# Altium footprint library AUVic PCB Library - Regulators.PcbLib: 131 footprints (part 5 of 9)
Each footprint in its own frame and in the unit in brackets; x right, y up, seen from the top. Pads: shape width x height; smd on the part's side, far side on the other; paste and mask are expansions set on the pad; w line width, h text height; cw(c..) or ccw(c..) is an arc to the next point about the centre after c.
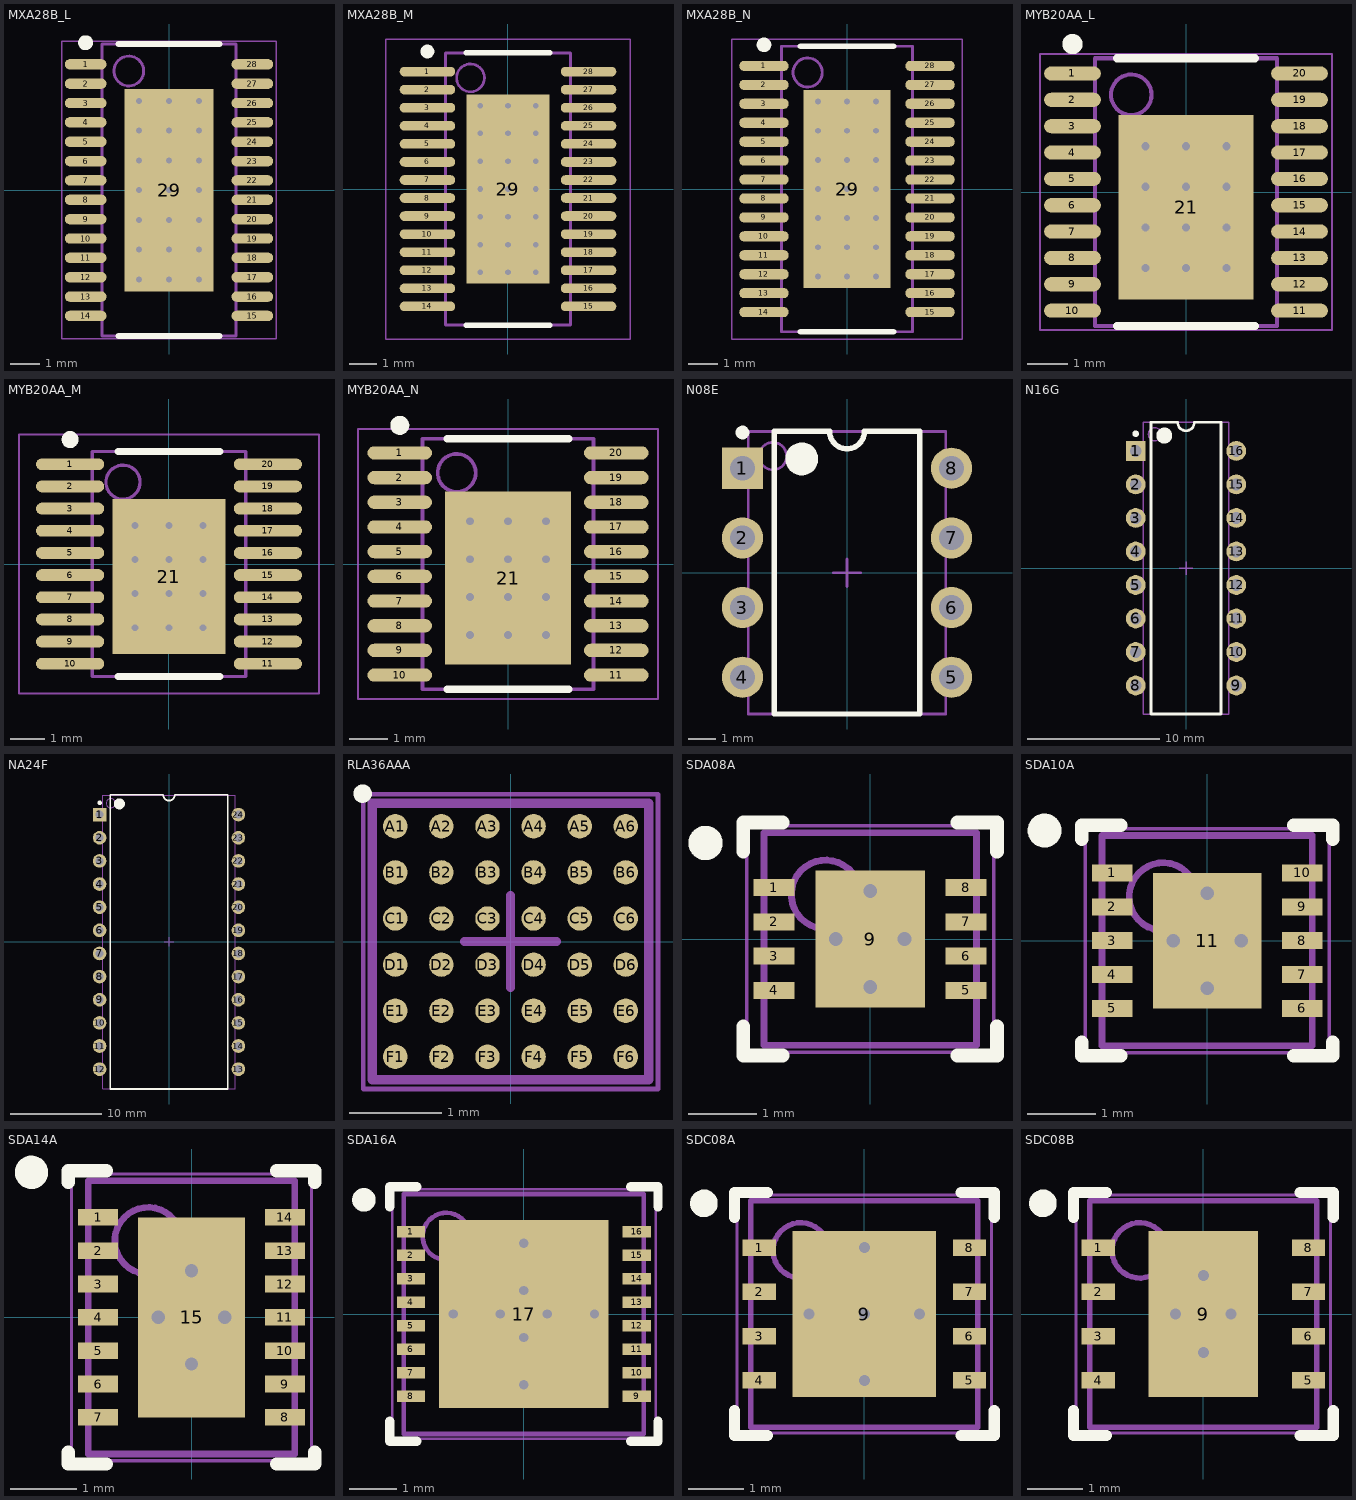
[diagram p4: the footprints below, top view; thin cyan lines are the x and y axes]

## MXA28B_L [mm] "TSOP, 28-Leads, Body 9.7x4.4mm, Pitch 0.65mm, Thermal Pad, IPC High Density"
height 1.1
pads (29):
  oval 1.4x0.35 smd: 1(-2.8,4.225) 2(-2.8,3.575) 3(-2.8,2.925) 4(-2.8,2.275) 5(-2.8,1.625) 6(-2.8,0.975) 7(-2.8,0.325) 8(-2.8,-0.325) 9(-2.8,-0.975) 10(-2.8,-1.625) 11(-2.8,-2.275) 12(-2.8,-2.925) 13(-2.8,-3.575) 14(-2.8,-4.225) 15(2.8,-4.225) 16(2.8,-3.575) 17(2.8,-2.925) 18(2.8,-2.275) 19(2.8,-1.625) 20(2.8,-0.975) 21(2.8,-0.325) 22(2.8,0.325) 23(2.8,0.975) 24(2.8,1.625) 25(2.8,2.275) 26(2.8,2.925) 27(2.8,3.575) 28(2.8,4.225)
  rect 3x6.8 smd: 29(0,0)
via 1,3 diameter 0.4 hole 0.2
via 0,3 diameter 0.4 hole 0.2
via -1,3 diameter 0.4 hole 0.2
via 0,0 diameter 0.4 hole 0.2
via 1,0 diameter 0.4 hole 0.2
via 0,-1 diameter 0.4 hole 0.2
via 1,-1 diameter 0.4 hole 0.2
via 0,-2 diameter 0.4 hole 0.2
via 1,-2 diameter 0.4 hole 0.2
via 1,1 diameter 0.4 hole 0.2
via 0,1 diameter 0.4 hole 0.2
via 1,-3 diameter 0.4 hole 0.2
via 0,-3 diameter 0.4 hole 0.2
via -1,-3 diameter 0.4 hole 0.2
via -1,1 diameter 0.4 hole 0.2
via -1,-2 diameter 0.4 hole 0.2
via -1,-1 diameter 0.4 hole 0.2
via -1,0 diameter 0.4 hole 0.2
via -1,2 diameter 0.4 hole 0.2
via 0,2 diameter 0.4 hole 0.2
via 1,2 diameter 0.4 hole 0.2
Top Overlay:
  circle w0.25: c-2.8,4.95 r0.125
  lines w0.2: -1.7,-4.9 1.7,-4.9 ; -1.7,4.9 1.7,4.9
Mechanical 13:
  circle w0.1: c-1.35,4 r0.5
  lines w0.1: -2.25,-4.9 -2.25,4.9 2.25,4.9 2.25,-4.9 -2.25,-4.9
Mechanical 15:
  lines w0.05: -3.6,-5 -3.6,5 3.6,5 3.6,-5 -3.6,-5
  lines w0.1: -0.5,0 0.5,0 ; 0,-0.5 0,0.5
3D body: height 1.1, standoff 0.05, extent -2.25,-4.9 2.25,4.9

## MXA28B_M [mm] "TSOP, 28-Leads, Body 9.7x4.4mm, Pitch 0.65mm, Thermal Pad, IPC Low Density"
height 1.1
pads (29):
  oval 2x0.35 smd: 1(-2.9,4.225) 2(-2.9,3.575) 3(-2.9,2.925) 4(-2.9,2.275) 5(-2.9,1.625) 6(-2.9,0.975) 7(-2.9,0.325) 8(-2.9,-0.325) 9(-2.9,-0.975) 10(-2.9,-1.625) 11(-2.9,-2.275) 12(-2.9,-2.925) 13(-2.9,-3.575) 14(-2.9,-4.225) 15(2.9,-4.225) 16(2.9,-3.575) 17(2.9,-2.925) 18(2.9,-2.275) 19(2.9,-1.625) 20(2.9,-0.975) 21(2.9,-0.325) 22(2.9,0.325) 23(2.9,0.975) 24(2.9,1.625) 25(2.9,2.275) 26(2.9,2.925) 27(2.9,3.575) 28(2.9,4.225)
  rect 3x6.8 smd: 29(0,0)
via 1,3 diameter 0.4 hole 0.2
via 0,3 diameter 0.4 hole 0.2
via -1,3 diameter 0.4 hole 0.2
via 0,0 diameter 0.4 hole 0.2
via 1,0 diameter 0.4 hole 0.2
via 0,-1 diameter 0.4 hole 0.2
via 1,-1 diameter 0.4 hole 0.2
via 0,-2 diameter 0.4 hole 0.2
via 1,-2 diameter 0.4 hole 0.2
via 1,1 diameter 0.4 hole 0.2
via 0,1 diameter 0.4 hole 0.2
via 1,-3 diameter 0.4 hole 0.2
via 0,-3 diameter 0.4 hole 0.2
via -1,-3 diameter 0.4 hole 0.2
via -1,1 diameter 0.4 hole 0.2
via -1,-2 diameter 0.4 hole 0.2
via -1,-1 diameter 0.4 hole 0.2
via -1,0 diameter 0.4 hole 0.2
via -1,2 diameter 0.4 hole 0.2
via 0,2 diameter 0.4 hole 0.2
via 1,2 diameter 0.4 hole 0.2
Top Overlay:
  circle w0.25: c-2.9,4.95 r0.125
  lines w0.2: -1.5,-4.9 1.5,-4.9 ; -1.5,4.9 1.5,4.9
Mechanical 13:
  circle w0.1: c-1.35,4 r0.5
  lines w0.1: -2.25,-4.9 -2.25,4.9 2.25,4.9 2.25,-4.9 -2.25,-4.9
Mechanical 15:
  lines w0.05: -4.4,-5.4 -4.4,5.4 4.4,5.4 4.4,-5.4 -4.4,-5.4
  lines w0.1: -0.5,0 0.5,0 ; 0,-0.5 0,0.5
3D body: height 1.1, standoff 0.05, extent -2.25,-4.9 2.25,4.9

## MXA28B_N [mm] "TSOP, 28-Leads, Body 9.7x4.4mm, Pitch 0.65mm, Thermal Pad, IPC Medium Density"
height 1.1
pads (29):
  oval 1.7x0.35 smd: 1(-2.85,4.225) 2(-2.85,3.575) 3(-2.85,2.925) 4(-2.85,2.275) 5(-2.85,1.625) 6(-2.85,0.975) 7(-2.85,0.325) 8(-2.85,-0.325) 9(-2.85,-0.975) 10(-2.85,-1.625) 11(-2.85,-2.275) 12(-2.85,-2.925) 13(-2.85,-3.575) 14(-2.85,-4.225) 15(2.85,-4.225) 16(2.85,-3.575) 17(2.85,-2.925) 18(2.85,-2.275) 19(2.85,-1.625) 20(2.85,-0.975) 21(2.85,-0.325) 22(2.85,0.325) 23(2.85,0.975) 24(2.85,1.625) 25(2.85,2.275) 26(2.85,2.925) 27(2.85,3.575) 28(2.85,4.225)
  rect 3x6.8 smd: 29(0,0)
via 1,2 diameter 0.4 hole 0.2
via 0,2 diameter 0.4 hole 0.2
via -1,2 diameter 0.4 hole 0.2
via -1,0 diameter 0.4 hole 0.2
via -1,-1 diameter 0.4 hole 0.2
via -1,-2 diameter 0.4 hole 0.2
via -1,1 diameter 0.4 hole 0.2
via -1,-3 diameter 0.4 hole 0.2
via 0,-3 diameter 0.4 hole 0.2
via 1,-3 diameter 0.4 hole 0.2
via 0,1 diameter 0.4 hole 0.2
via 1,1 diameter 0.4 hole 0.2
via 1,-2 diameter 0.4 hole 0.2
via 0,-2 diameter 0.4 hole 0.2
via 1,-1 diameter 0.4 hole 0.2
via 0,-1 diameter 0.4 hole 0.2
via 1,0 diameter 0.4 hole 0.2
via 0,0 diameter 0.4 hole 0.2
via -1,3 diameter 0.4 hole 0.2
via 0,3 diameter 0.4 hole 0.2
via 1,3 diameter 0.4 hole 0.2
Top Overlay:
  circle w0.25: c-2.85,4.95 r0.125
  lines w0.2: -1.6,-4.9 1.6,-4.9 ; -1.6,4.9 1.6,4.9
Mechanical 13:
  circle w0.1: c-1.35,4 r0.5
  lines w0.1: -2.25,-4.9 2.25,-4.9 2.25,4.9 -2.25,4.9 -2.25,-4.9
Mechanical 15:
  lines w0.05: -3.95,-5.15 3.95,-5.15 3.95,5.15 -3.95,5.15 -3.95,-5.15
  lines w0.1: -0.5,0 0.5,0 ; 0,-0.5 0,0.5
3D body: height 1.1, standoff 0.05, extent -2.25,-4.9 2.25,4.9

## MYB20AA_L [mm] "TSOP, 20-Leads, Body 6.5x4.4mm, Pitch 0.65mm, Thermal Pad, IPC High Density"
height 1.1
pads (21):
  oval 1.4x0.35 smd: 1(-2.8,2.925) 2(-2.8,2.275) 3(-2.8,1.625) 4(-2.8,0.975) 5(-2.8,0.325) 6(-2.8,-0.325) 7(-2.8,-0.975) 8(-2.8,-1.625) 9(-2.8,-2.275) 10(-2.8,-2.925) 11(2.8,-2.925) 12(2.8,-2.275) 13(2.8,-1.625) 14(2.8,-0.975) 15(2.8,-0.325) 16(2.8,0.325) 17(2.8,0.975) 18(2.8,1.625) 19(2.8,2.275) 20(2.8,2.925)
  rect 3.32x4.55 smd: 21(0,-0.37)
via 0,0.13 diameter 0.5 hole 0.2
via 1,0.13 diameter 0.5 hole 0.2
via 0,-0.87 diameter 0.5 hole 0.2
via 1,-0.87 diameter 0.5 hole 0.2
via 0,-1.87 diameter 0.5 hole 0.2
via 1,-1.87 diameter 0.5 hole 0.2
via -1,-1.87 diameter 0.5 hole 0.2
via -1,-0.87 diameter 0.5 hole 0.2
via -1,0.13 diameter 0.5 hole 0.2
via -1,1.13 diameter 0.5 hole 0.2
via 1,1.13 diameter 0.5 hole 0.2
via 0,1.13 diameter 0.5 hole 0.2
Top Overlay:
  circle w0.25: c-2.8,3.65 r0.125
  lines w0.2: -1.7,-3.3 1.7,-3.3 ; -1.7,3.3 1.7,3.3
Mechanical 13:
  circle w0.1: c-1.35,2.4 r0.5
  lines w0.1: -2.25,-3.3 2.25,-3.3 2.25,3.3 -2.25,3.3 -2.25,-3.3
Mechanical 15:
  lines w0.05: -3.6,-3.4 3.6,-3.4 3.6,3.4 -3.6,3.4 -3.6,-3.4
  lines w0.1: -0.5,0 0.5,0 ; 0,-0.5 0,0.5
3D body: height 1.1, standoff 0.05, extent -2.25,-3.3 2.25,3.3

## MYB20AA_M [mm] "TSOP, 20-Leads, Body 6.5x4.4mm, Pitch 0.65mm, Thermal Pad, IPC Low Density"
height 1.1
pads (21):
  oval 2x0.35 smd: 1(-2.9,2.925) 2(-2.9,2.275) 3(-2.9,1.625) 4(-2.9,0.975) 5(-2.9,0.325) 6(-2.9,-0.325) 7(-2.9,-0.975) 8(-2.9,-1.625) 9(-2.9,-2.275) 10(-2.9,-2.925) 11(2.9,-2.925) 12(2.9,-2.275) 13(2.9,-1.625) 14(2.9,-0.975) 15(2.9,-0.325) 16(2.9,0.325) 17(2.9,0.975) 18(2.9,1.625) 19(2.9,2.275) 20(2.9,2.925)
  rect 3.32x4.55 smd: 21(0,-0.37)
via 0,1.13 diameter 0.5 hole 0.2
via 1,1.13 diameter 0.5 hole 0.2
via -1,1.13 diameter 0.5 hole 0.2
via -1,0.13 diameter 0.5 hole 0.2
via -1,-0.87 diameter 0.5 hole 0.2
via -1,-1.87 diameter 0.5 hole 0.2
via 1,-1.87 diameter 0.5 hole 0.2
via 0,-1.87 diameter 0.5 hole 0.2
via 1,-0.87 diameter 0.5 hole 0.2
via 0,-0.87 diameter 0.5 hole 0.2
via 1,0.13 diameter 0.5 hole 0.2
via 0,0.13 diameter 0.5 hole 0.2
Top Overlay:
  circle w0.25: c-2.9,3.65 r0.125
  lines w0.2: -1.5,-3.3 1.5,-3.3 ; -1.5,3.3 1.5,3.3
Mechanical 13:
  circle w0.1: c-1.35,2.4 r0.5
  lines w0.1: -2.25,-3.3 -2.25,3.3 2.25,3.3 2.25,-3.3 -2.25,-3.3
Mechanical 15:
  lines w0.05: -4.4,-3.8 -4.4,3.8 4.4,3.8 4.4,-3.8 -4.4,-3.8
  lines w0.1: -0.5,0 0.5,0 ; 0,-0.5 0,0.5
3D body: height 1.1, standoff 0.05, extent -2.25,-3.3 2.25,3.3

## MYB20AA_N [mm] "TSOP, 20-Leads, Body 6.5x4.4mm, Pitch 0.65mm, Thermal Pad, IPC Medium Density"
height 1.1
pads (21):
  oval 1.7x0.35 smd: 1(-2.85,2.925) 2(-2.85,2.275) 3(-2.85,1.625) 4(-2.85,0.975) 5(-2.85,0.325) 6(-2.85,-0.325) 7(-2.85,-0.975) 8(-2.85,-1.625) 9(-2.85,-2.275) 10(-2.85,-2.925) 11(2.85,-2.925) 12(2.85,-2.275) 13(2.85,-1.625) 14(2.85,-0.975) 15(2.85,-0.325) 16(2.85,0.325) 17(2.85,0.975) 18(2.85,1.625) 19(2.85,2.275) 20(2.85,2.925)
  rect 3.32x4.55 smd: 21(0,-0.37)
via 0,0.13 diameter 0.5 hole 0.2
via 1,0.13 diameter 0.5 hole 0.2
via 0,-0.87 diameter 0.5 hole 0.2
via 1,-0.87 diameter 0.5 hole 0.2
via 0,-1.87 diameter 0.5 hole 0.2
via 1,-1.87 diameter 0.5 hole 0.2
via -1,-1.87 diameter 0.5 hole 0.2
via -1,-0.87 diameter 0.5 hole 0.2
via -1,0.13 diameter 0.5 hole 0.2
via -1,1.13 diameter 0.5 hole 0.2
via 1,1.13 diameter 0.5 hole 0.2
via 0,1.13 diameter 0.5 hole 0.2
Top Overlay:
  circle w0.25: c-2.85,3.65 r0.125
  lines w0.2: -1.6,-3.3 1.6,-3.3 ; -1.6,3.3 1.6,3.3
Mechanical 13:
  circle w0.1: c-1.35,2.4 r0.5
  lines w0.1: -2.25,-3.3 2.25,-3.3 2.25,3.3 -2.25,3.3 -2.25,-3.3
Mechanical 15:
  lines w0.05: -3.95,-3.55 3.95,-3.55 3.95,3.55 -3.95,3.55 -3.95,-3.55
  lines w0.1: -0.5,0 0.5,0 ; 0,-0.5 0,0.5
3D body: height 1.1, standoff 0.05, extent -2.25,-3.3 2.25,3.3

## N08E [mm] "DIP, 8-Pin, Row Spacing 7.62 mm, Pitch 2.54 mm"
height 5.34
pads (8):
  rect 1.5x1.5 hole 0.9: 1(-3.81,3.81)
  round 1.5 hole 0.9: 2(-3.81,1.27) 3(-3.81,-1.27) 4(-3.81,-3.81) 5(3.81,-3.81) 6(3.81,-1.27) 7(3.81,1.27) 8(3.81,3.81)
Top Overlay:
  circle w0.6: c-1.65,4.15 r0.3
  circle w0.25: c-3.81,5.11 r0.125
  lines w0.2: -2.65,-5.15 2.65,-5.15 2.65,5.15 0.635,5.15 cw(c0,5.15) -0.635,5.15 -2.65,5.15 -2.65,-5.15
Mechanical 13:
  circle w0.1: c-2.7,4.25 r0.5
  lines w0.1: -3.6,-5.15 3.6,-5.15 3.6,5.15 -3.6,5.15 -3.6,-5.15
Mechanical 15:
  lines w0.1: -0.5,0 0.5,0 ; 0,-0.5 0,0.5
3D body: height 5.34, standoff 0, extent -3.6,-5.15 3.6,5.15

## N16G [mm] "DIP, 16-Pin, Row Spacing 7.62 mm, Pitch 2.54 mm"
height 5.08
pads (16):
  rect 1.5x1.5 hole 0.9: 1(-3.81,8.89)
  round 1.5 hole 0.9: 2(-3.81,6.35) 3(-3.81,3.81) 4(-3.81,1.27) 5(-3.81,-1.27) 6(-3.81,-3.81) 7(-3.81,-6.35) 8(-3.81,-8.89) 9(3.81,-8.89) 10(3.81,-6.35) 11(3.81,-3.81) 12(3.81,-1.27) 13(3.81,1.27) 14(3.81,3.81) 15(3.81,6.35) 16(3.81,8.89)
Top Overlay:
  circle w0.6: c-1.65,10.05 r0.3
  circle w0.25: c-3.81,10.19 r0.125
  lines w0.2: -2.65,-11.05 2.65,-11.05 2.65,11.05 0.635,11.05 cw(c0,11.05) -0.635,11.05 -2.65,11.05 -2.65,-11.05
Mechanical 13:
  circle w0.1: c-2.35,10.15 r0.5
  lines w0.1: -3.25,-11.05 3.25,-11.05 3.25,11.05 -3.25,11.05 -3.25,-11.05
Mechanical 15:
  lines w0.1: -0.5,0 0.5,0 ; 0,-0.5 0,0.5
3D body: height 5.08, standoff 0, extent -3.25,-11.05 3.25,11.05

## NA24F [mm] "DIP, 24-Pin, Row Spacing 15.24 mm, Pitch 2.54 mm"
height 7.24
pads (24):
  rect 1.5x1.5 hole 0.9: 1(-7.62,13.97)
  round 1.5 hole 0.9: 2(-7.62,11.43) 3(-7.62,8.89) 4(-7.62,6.35) 5(-7.62,3.81) 6(-7.62,1.27) 7(-7.62,-1.27) 8(-7.62,-3.81) 9(-7.62,-6.35) 10(-7.62,-8.89) 11(-7.62,-11.43) 12(-7.62,-13.97) 13(7.62,-13.97) 14(7.62,-11.43) 15(7.62,-8.89) 16(7.62,-6.35) 17(7.62,-3.81) 18(7.62,-1.27) 19(7.62,1.27) 20(7.62,3.81) 21(7.62,6.35) 22(7.62,8.89) 23(7.62,11.43) 24(7.62,13.97)
Top Overlay:
  circle w0.25: c-7.62,15.27 r0.125
  circle w0.6: c-5.45,15.15 r0.3
  lines w0.2: -6.45,-16.15 -6.45,16.15 -0.635,16.15 ccw(c0,16.15) 0.635,16.15 6.45,16.15 6.45,-16.15 -6.45,-16.15
Mechanical 13:
  circle w0.1: c-6.4,15.225 r0.5
  lines w0.1: -7.3,-16.125 -7.3,16.125 7.3,16.125 7.3,-16.125 -7.3,-16.125
Mechanical 15:
  lines w0.1: -0.5,0 0.5,0 ; 0,-0.5 0,0.5
3D body: height 7.24, standoff 0, extent -7.3,-16.125 7.3,16.125

## RLA36AAA [mm] "Micro SMD, 36-Leads, Body 3x3mm, Pitch 0.5mm, NSC Recommended"
height 0.73
pads (36):
  round 0.265 smd paste-0.132 mask+0.05: A1(-1.25,1.25) A2(-0.75,1.25) A3(-0.25,1.25) A4(0.25,1.25) A5(0.75,1.25) A6(1.25,1.25) B1(-1.25,0.75) B2(-0.75,0.75) B3(-0.25,0.75) B4(0.25,0.75) B5(0.75,0.75) B6(1.25,0.75) C1(-1.25,0.25) C2(-0.75,0.25) C3(-0.25,0.25) C4(0.25,0.25) C5(0.75,0.25) C6(1.25,0.25) D1(-1.25,-0.25) D2(-0.75,-0.25) D3(-0.25,-0.25) D4(0.25,-0.25) D5(0.75,-0.25) D6(1.25,-0.25) E1(-1.25,-0.75) E2(-0.75,-0.75) E3(-0.25,-0.75) E4(0.25,-0.75) E5(0.75,-0.75) E6(1.25,-0.75) F1(-1.25,-1.25) F2(-0.75,-1.25) F3(-0.25,-1.25) F4(0.25,-1.25) F5(0.75,-1.25) F6(1.25,-1.25)
Top Overlay:
  circle w0.1: c-1.605,1.605 r0.05
Top Paste:
  drawing of 324 lines, arcs and shapes, not listed
Mechanical 13:
  lines w0.1: -1.5,-1.5 -1.5,1.5 1.5,1.5 1.5,-1.5 -1.5,-1.5
Mechanical 15:
  lines w0.05: -1.6,-1.6 -1.6,1.6 1.6,1.6 1.6,-1.6 -1.6,-1.6
  lines w0.1: -0.5,0 0.5,0 ; 0,-0.5 0,0.5
3D body: height 0.73, standoff 0, extent -1.5,-1.5 1.5,1.5

## SDA08A [mm] "SON, 8-Leads, Body 3x3mm, Pitch 0.5mm, NSC Recommended"
height 0.8
pads (9):
  rect 0.6x0.25 smd paste-0.125 mask+0.051: 1(-1.4,0.75) 2(-1.4,0.25) 3(-1.4,-0.25) 4(-1.4,-0.75) 5(1.4,-0.75) 6(1.4,-0.25) 7(1.4,0.25) 8(1.4,0.75)
  rect 1.6x2 smd paste-0.05 mask+0.051: 9(0,0)
via -0.5,0 diameter 0.5 hole 0.2
via 0.5,0 diameter 0.5 hole 0.2
via 0,0.7 diameter 0.5 hole 0.2
via 0,-0.7 diameter 0.5 hole 0.2
Top Overlay:
  circle w0.25: c-2.4,1.4 r0.125
  lines w0.2: -1.85,-1.275 -1.85,-1.7 -1.275,-1.7 ; -1.85,1.275 -1.85,1.7 -1.275,1.7 ; 1.275,-1.7 1.85,-1.7 1.85,-1.275 ; 1.275,1.7 1.85,1.7 1.85,1.275
Top Paste:
  region: 1.2,0.875 1.2,0.625 1.9,0.625 1.9,0.875
  region: 1.2,0.375 1.2,0.125 1.9,0.125 1.9,0.375
  region: 1.2,-0.125 1.2,-0.375 1.9,-0.375 1.9,-0.125
  region: 1.2,-0.625 1.2,-0.875 1.9,-0.875 1.9,-0.625
  region: -1.9,-0.625 -1.9,-0.875 -1.2,-0.875 -1.2,-0.625
  region: -1.9,-0.125 -1.9,-0.375 -1.2,-0.375 -1.2,-0.125
  region: -1.9,0.375 -1.9,0.125 -1.2,0.125 -1.2,0.375
  region: -1.9,0.875 -1.9,0.625 -1.2,0.625 -1.2,0.875
Mechanical 13:
  circle w0.1: c-0.65,0.65 r0.5
  lines w0.1: -1.55,-1.55 1.55,-1.55 1.55,1.55 -1.55,1.55 -1.55,-1.55
Mechanical 15:
  lines w0.05: -1.8,-1.65 1.8,-1.65 1.8,1.65 -1.8,1.65 -1.8,-1.65
  lines w0.1: -0.5,0 0.5,0 ; 0,-0.5 0,0.5
3D body: height 0.8, standoff 0, extent -1.55,-1.55 1.55,1.55

## SDA10A [mm] "SON, 10-Leads, Body 3x3 mm, Pitch 0.5mm, NSC Recommended"
height 0.8
pads (11):
  rect 0.6x0.25 smd paste-0.125 mask+0.051: 1(-1.4,1) 2(-1.4,0.5) 3(-1.4,0) 4(-1.4,-0.5) 5(-1.4,-1) 6(1.4,-1) 7(1.4,-0.5) 8(1.4,0) 9(1.4,0.5) 10(1.4,1)
  rect 1.6x2 smd paste-0.05 mask+0.051: 11(0,0)
via -0.5,0 diameter 0.5 hole 0.2
via 0.5,0 diameter 0.5 hole 0.2
via 0,0.7 diameter 0.5 hole 0.2
via 0,-0.7 diameter 0.5 hole 0.2
Top Overlay:
  circle w0.25: c-2.4,1.625 r0.125
  lines w0.2: -1.85,-1.5 -1.85,-1.7 -1.275,-1.7 ; -1.85,1.5 -1.85,1.7 -1.275,1.7 ; 1.275,-1.7 1.85,-1.7 1.85,-1.5 ; 1.275,1.7 1.85,1.7 1.85,1.5
Top Paste:
  rectangle: -1.9,0.875 -1.2,1.125
  rectangle: -1.9,0.375 -1.2,0.625
  rectangle: -1.9,-0.125 -1.2,0.125
  rectangle: -1.9,-0.625 -1.2,-0.375
  rectangle: -1.9,-1.125 -1.2,-0.875
  region: 1.9,1.125 1.2,1.125 1.2,0.875 1.9,0.875
  region: 1.9,0.625 1.2,0.625 1.2,0.375 1.9,0.375
  region: 1.9,0.125 1.2,0.125 1.2,-0.125 1.9,-0.125
  region: 1.9,-0.375 1.2,-0.375 1.2,-0.625 1.9,-0.625
  region: 1.9,-0.875 1.2,-0.875 1.2,-1.125 1.9,-1.125
Mechanical 13:
  circle w0.1: c-0.65,0.65 r0.5
  lines w0.1: -1.55,-1.55 -1.55,1.55 1.55,1.55 1.55,-1.55 -1.55,-1.55
Mechanical 15:
  lines w0.05: -1.8,-1.65 -1.8,1.65 1.8,1.65 1.8,-1.65 -1.8,-1.65
  lines w0.1: -0.5,0 0.5,0 ; 0,-0.5 0,0.5
3D body: height 0.8, standoff 0, extent -1.55,-1.55 1.55,1.55

## SDA14A [mm] "SON, 14-Leads, Body 4x3mm, Pitch 0.5mm, NSC Recommended"
height 0.8
pads (15):
  rect 0.6x0.25 smd paste-0.125 mask+0.051: 1(-1.4,1.5) 2(-1.4,1) 3(-1.4,0.5) 4(-1.4,0) 5(-1.4,-0.5) 6(-1.4,-1) 7(-1.4,-1.5) 8(1.4,-1.5) 9(1.4,-1) 10(1.4,-0.5) 11(1.4,0) 12(1.4,0.5) 13(1.4,1) 14(1.4,1.5)
  rect 1.6x3 smd paste-0.8 mask+0.051: 15(0,0)
via -0.5,0 diameter 0.5 hole 0.2
via 0.5,0 diameter 0.5 hole 0.2
via 0,0.7 diameter 0.5 hole 0.2
via 0,-0.7 diameter 0.5 hole 0.2
Top Overlay:
  circle w0.25: c-2.4,2.175 r0.125
  lines w0.2: -1.85,-2.025 -1.85,-2.2 -1.275,-2.2 ; -1.85,2.025 -1.85,2.2 -1.275,2.2 ; 1.275,-2.2 1.85,-2.2 1.85,-2.025 ; 1.275,2.2 1.85,2.2 1.85,2.025
Top Paste:
  region: -0.7,-0.1 -0.7,-1.4 -0.1,-1.4 -0.1,-0.1
  region: -0.1,0.1 -0.1,1.4 -0.7,1.4 -0.7,0.1
  region: 0.7,0.1 0.7,1.4 0.1,1.4 0.1,0.1
  region: 0.1,-0.1 0.1,-1.4 0.7,-1.4 0.7,-0.1
  region: 1.2,1.625 1.2,1.375 1.9,1.375 1.9,1.625
  region: 1.2,1.125 1.2,0.875 1.9,0.875 1.9,1.125
  region: 1.2,0.625 1.2,0.375 1.9,0.375 1.9,0.625
  region: 1.2,0.125 1.2,-0.125 1.9,-0.125 1.9,0.125
  region: 1.2,-0.375 1.2,-0.625 1.9,-0.625 1.9,-0.375
  region: 1.2,-0.875 1.2,-1.125 1.9,-1.125 1.9,-0.875
  region: 1.2,-1.375 1.2,-1.625 1.9,-1.625 1.9,-1.375
  region: -1.9,-1.375 -1.9,-1.625 -1.2,-1.625 -1.2,-1.375
  region: -1.9,-0.875 -1.9,-1.125 -1.2,-1.125 -1.2,-0.875
  region: -1.9,-0.375 -1.9,-0.625 -1.2,-0.625 -1.2,-0.375
  region: -1.9,0.125 -1.9,-0.125 -1.2,-0.125 -1.2,0.125
  region: -1.9,0.625 -1.9,0.375 -1.2,0.375 -1.2,0.625
  region: -1.9,1.125 -1.9,0.875 -1.2,0.875 -1.2,1.125
  region: -1.9,1.625 -1.9,1.375 -1.2,1.375 -1.2,1.625
Mechanical 13:
  circle w0.1: c-0.65,1.15 r0.5
  lines w0.1: -1.55,-2.05 1.55,-2.05 1.55,2.05 -1.55,2.05 -1.55,-2.05
Mechanical 15:
  lines w0.05: -1.8,-2.15 1.8,-2.15 1.8,2.15 -1.8,2.15 -1.8,-2.15
  lines w0.1: -0.5,0 0.5,0 ; 0,-0.5 0,0.5
3D body: height 0.8, standoff 0, extent -1.55,-2.05 1.55,2.05

## SDA16A [mm] "SON, 16-Leads, Body 5x5mm, Pitch 0.5mm, NSC Recommended"
height 0.8
pads (17):
  rect 0.6x0.25 smd paste-0.125 mask+0.051: 1(-2.4,1.75) 2(-2.4,1.25) 3(-2.4,0.75) 4(-2.4,0.25) 5(-2.4,-0.25) 6(-2.4,-0.75) 7(-2.4,-1.25) 8(-2.4,-1.75) 9(2.4,-1.75) 10(2.4,-1.25) 11(2.4,-0.75) 12(2.4,-0.25) 13(2.4,0.25) 14(2.4,0.75) 15(2.4,1.25) 16(2.4,1.75)
  rect 3.6x4 smd paste-1.8 mask+0.051: 17(0,0)
via -1.5,0 diameter 0.5 hole 0.2
via 0,-1.5 diameter 0.5 hole 0.2
via 0,1.5 diameter 0.5 hole 0.2
via 1.5,0 diameter 0.5 hole 0.2
via -0.5,0 diameter 0.5 hole 0.2
via 0.5,0 diameter 0.5 hole 0.2
via 0,-0.5 diameter 0.5 hole 0.2
via 0,0.5 diameter 0.5 hole 0.2
Top Overlay:
  circle w0.25: c-3.4,2.425 r0.125
  lines w0.2: -2.85,-2.275 -2.85,-2.7 -2.275,-2.7 ; -2.85,2.275 -2.85,2.7 -2.275,2.7 ; 2.275,-2.7 2.85,-2.7 2.85,-2.275 ; 2.275,2.7 2.85,2.7 2.85,2.275
Top Paste:
  region: -1.7,-0.1 -1.7,-1.9 -0.1,-1.9 -0.1,-0.1
  region: -0.1,0.1 -0.1,1.9 -1.7,1.9 -1.7,0.1
  region: 1.7,0.1 1.7,1.9 0.1,1.9 0.1,0.1
  region: 2.2,1.875 2.2,1.625 2.9,1.625 2.9,1.875
  region: 2.2,1.375 2.2,1.125 2.9,1.125 2.9,1.375
  region: 2.2,0.875 2.2,0.625 2.9,0.625 2.9,0.875
  region: 2.2,0.375 2.2,0.125 2.9,0.125 2.9,0.375
  region: 2.2,-0.125 2.2,-0.375 2.9,-0.375 2.9,-0.125
  region: 2.2,-0.625 2.2,-0.875 2.9,-0.875 2.9,-0.625
  region: 2.2,-1.125 2.2,-1.375 2.9,-1.375 2.9,-1.125
  region: 2.2,-1.625 2.2,-1.875 2.9,-1.875 2.9,-1.625
  region: -2.9,-1.625 -2.9,-1.875 -2.2,-1.875 -2.2,-1.625
  region: -2.9,-1.125 -2.9,-1.375 -2.2,-1.375 -2.2,-1.125
  region: -2.9,-0.625 -2.9,-0.875 -2.2,-0.875 -2.2,-0.625
  region: -2.9,-0.125 -2.9,-0.375 -2.2,-0.375 -2.2,-0.125
  region: -2.9,0.375 -2.9,0.125 -2.2,0.125 -2.2,0.375
  region: -2.9,0.875 -2.9,0.625 -2.2,0.625 -2.2,0.875
  region: -2.9,1.375 -2.9,1.125 -2.2,1.125 -2.2,1.375
  region: -2.9,1.875 -2.9,1.625 -2.2,1.625 -2.2,1.875
  region: 0.1,-0.1 0.1,-1.9 1.7,-1.9 1.7,-0.1
Mechanical 13:
  circle w0.1: c-1.65,1.65 r0.5
  lines w0.1: -2.55,-2.55 -2.55,2.55 2.55,2.55 2.55,-2.55 -2.55,-2.55
Mechanical 15:
  lines w0.05: -2.8,-2.65 -2.8,2.65 2.8,2.65 2.8,-2.65 -2.8,-2.65
  lines w0.1: -0.5,0 0.5,0 ; 0,-0.5 0,0.5
3D body: height 0.8, standoff 0, extent -2.55,-2.55 2.55,2.55

## SDC08A [mm] "SON, 8-Leads, Body 4x4mm, Pitch 0.8mm, NSC Recommended"
height 0.8
pads (9):
  rect 0.6x0.3 smd paste-0.15 mask+0.051: 1(-1.9,1.2) 2(-1.9,0.4) 3(-1.9,-0.4) 4(-1.9,-1.2) 5(1.9,-1.2) 6(1.9,-0.4) 7(1.9,0.4) 8(1.9,1.2)
  rect 2.6x3 smd paste-1.5 mask+0.051: 9(0,0)
via -1,0 diameter 0.5 hole 0.2
via 0,0 diameter 0.5 hole 0.2
via 1,0 diameter 0.5 hole 0.2
via 0,1.2 diameter 0.5 hole 0.2
via 0,-1.2 diameter 0.5 hole 0.2
Top Overlay:
  circle w0.25: c-2.9,2 r0.125
  lines w0.2: -2.35,-1.75 -2.35,-2.2 -1.75,-2.2 ; -2.35,1.75 -2.35,2.2 -1.75,2.2 ; 1.75,-2.2 2.35,-2.2 2.35,-1.75 ; 1.75,2.2 2.35,2.2 2.35,1.75
Top Paste:
  rectangle: -1.2,-1.4 -0.1,-0.1
  region: 1.2,-0.1 0.1,-0.1 0.1,-1.4 1.2,-1.4
  region: 1.2,1.4 0.1,1.4 0.1,0.1 1.2,0.1
  rectangle: -1.2,0.1 -0.1,1.4
  rectangle: 1.7,1.05 2.4,1.35
  rectangle: 1.7,0.25 2.4,0.55
  rectangle: 1.7,-0.55 2.4,-0.25
  rectangle: 1.7,-1.35 2.4,-1.05
  region: -1.7,-1.05 -2.4,-1.05 -2.4,-1.35 -1.7,-1.35
  region: -1.7,-0.25 -2.4,-0.25 -2.4,-0.55 -1.7,-0.55
  region: -1.7,0.55 -2.4,0.55 -2.4,0.25 -1.7,0.25
  region: -1.7,1.35 -2.4,1.35 -2.4,1.05 -1.7,1.05
Mechanical 13:
  circle w0.1: c-1.15,1.15 r0.5
  lines w0.1: -2.05,-2.05 2.05,-2.05 2.05,2.05 -2.05,2.05 -2.05,-2.05
Mechanical 15:
  lines w0.05: -2.3,-2.15 2.3,-2.15 2.3,2.15 -2.3,2.15 -2.3,-2.15
  lines w0.1: -0.5,0 0.5,0 ; 0,-0.5 0,0.5
3D body: height 0.8, standoff 0, extent -2.05,-2.05 2.05,2.05

## SDC08B [mm] "SON, 8-Leads, Body 4x4mm, Pitch 0.8mm, NSC Recommended"
height 0.8
pads (9):
  rect 0.6x0.3 smd paste-0.15 mask+0.051: 1(-1.9,1.2) 2(-1.9,0.4) 3(-1.9,-0.4) 4(-1.9,-1.2) 5(1.9,-1.2) 6(1.9,-0.4) 7(1.9,0.4) 8(1.9,1.2)
  rect 1.98x3 smd paste-1.5 mask+0.051: 9(0,0)
via 0,-0.7 diameter 0.5 hole 0.2
via 0,0.7 diameter 0.5 hole 0.2
via 0.5,0 diameter 0.5 hole 0.2
via -0.5,0 diameter 0.5 hole 0.2
Top Overlay:
  circle w0.25: c-2.9,2 r0.125
  lines w0.2: -2.35,-1.75 -2.35,-2.2 -1.75,-2.2 ; -2.35,1.75 -2.35,2.2 -1.75,2.2 ; 1.75,-2.2 2.35,-2.2 2.35,-1.75 ; 1.75,2.2 2.35,2.2 2.35,1.75
Top Paste:
  region: 0.99,1.5 0.1,1.5 0.1,0.1 0.99,0.1
  rectangle: -0.99,-1.5 -0.1,-0.1
  region: 0.99,-0.1 0.1,-0.1 0.1,-1.5 0.99,-1.5
  region: -1.7,1.35 -2.4,1.35 -2.4,1.05 -1.7,1.05
  region: -1.7,0.55 -2.4,0.55 -2.4,0.25 -1.7,0.25
  region: -1.7,-0.25 -2.4,-0.25 -2.4,-0.55 -1.7,-0.55
  region: -1.7,-1.05 -2.4,-1.05 -2.4,-1.35 -1.7,-1.35
  rectangle: 1.7,-1.35 2.4,-1.05
  rectangle: 1.7,-0.55 2.4,-0.25
  rectangle: 1.7,0.25 2.4,0.55
  rectangle: 1.7,1.05 2.4,1.35
  rectangle: -0.99,0.1 -0.1,1.5
Mechanical 13:
  circle w0.1: c-1.15,1.15 r0.5
  lines w0.1: -2.05,-2.05 -2.05,2.05 2.05,2.05 2.05,-2.05 -2.05,-2.05
Mechanical 15:
  lines w0.05: -2.3,-2.15 -2.3,2.15 2.3,2.15 2.3,-2.15 -2.3,-2.15
  lines w0.1: -0.5,0 0.5,0 ; 0,-0.5 0,0.5
3D body: height 0.8, standoff 0, extent -2.05,-2.05 2.05,2.05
